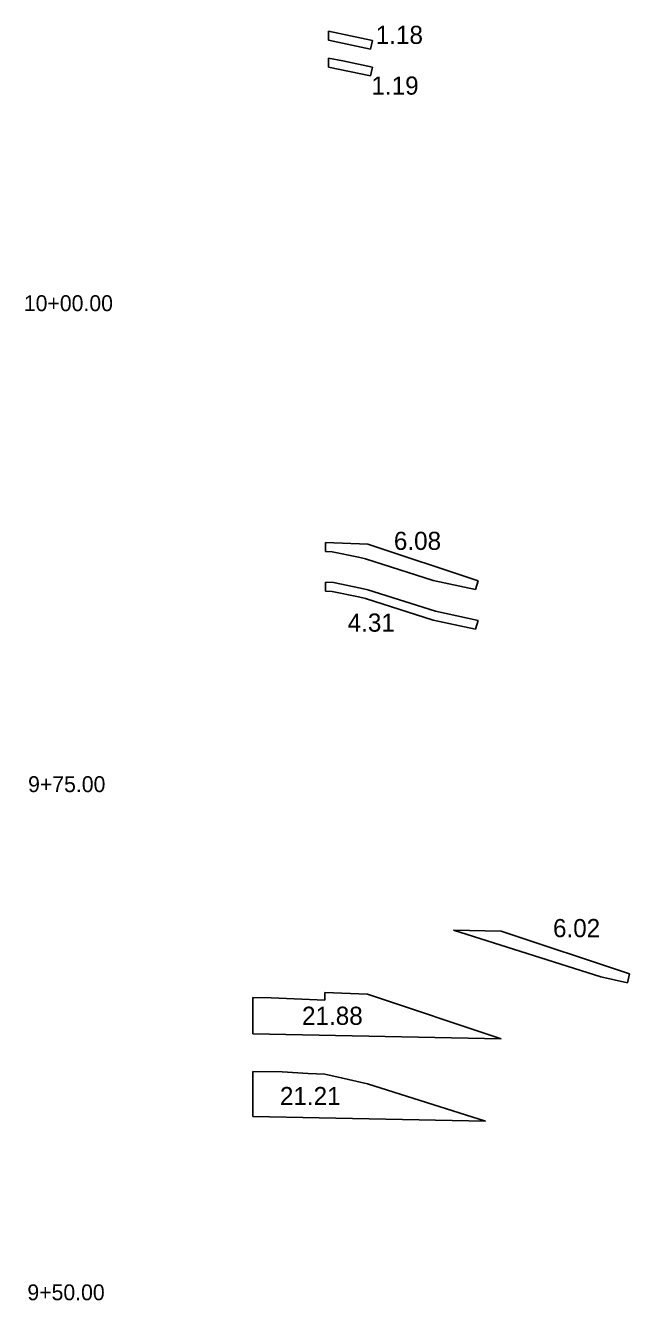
# Model space of a CAD drawing. Extents: x 2194738 to 2195190, y 863888 to 863998.
# Drawn here: x 2194737.6 to 2194770.9, y 863895.1 to 863965.3 of the extents above; entities that cross this region are included whole.
import ezdxf

# ---------------------------------------------------------------- set-up
doc = ezdxf.new("R2010")
doc.units = 0
for name, color, linetype in [('Approach', 7, 'Continuous'), ('H_V ANNOTATION', 7, 'Continuous'), ('S_Roadway_Centerline', 7, 'Continuous'), ('TEMPLATE', 7, 'Continuous')]:
    doc.layers.add(name, color=color, linetype=linetype)

msp = doc.modelspace()

# ---------------------------------------------------------------- linework, layer by layer
at = {"layer": 'S_Roadway_Centerline'}
for points in [[(2194754.353, 863963.517), (2194755.134, 863963.356), (2194756.768, 863963.011)], [(2194754.621, 863934.625), (2194756.106, 863934.311), (2194756.523, 863934.214), (2194760.247, 863933.034), (2194762.606, 863932.521)], [(2194750.176, 863907.678), (2194751.8, 863907.66), (2194753.226, 863907.572), (2194754.139, 863907.522), (2194755.051, 863907.329), (2194756.506, 863906.993), (2194763.003, 863904.934)]]:
    msp.add_lwpolyline(points, dxfattribs=at)
at = {"layer": 'TEMPLATE'}
for p, q in [((2194754.353, 863964.997), (2194756.768, 863964.491)), ((2194756.768, 863964.491), (2194756.668, 863964.012)), ((2194756.768, 863963.011), (2194756.668, 863962.532)), ((2194754.185, 863936.827), (2194754.185, 863936.702)), ((2194754.185, 863936.827), (2194756.523, 863936.734)), ((2194756.523, 863936.734), (2194762.606, 863934.706)), ((2194754.185, 863934.643), (2194754.185, 863934.518)), ((2194754.185, 863934.643), (2194754.621, 863934.625)), ((2194763.878, 863915.412), (2194761.236, 863915.465)), ((2194770.948, 863913.056), (2194770.841, 863912.567)), ((2194756.506, 863911.933), (2194754.139, 863912.028)), ((2194754.139, 863911.611), (2194754.139, 863912.028)), ((2194751.176, 863911.73), (2194750.176, 863911.75)), ((2194750.176, 863909.75), (2194750.176, 863911.75)), ((2194754.139, 863911.611), (2194751.176, 863911.73)), ((2194763.878, 863909.476), (2194750.176, 863909.75)), ((2194750.176, 863905.191), (2194750.176, 863907.678)), ((2194763.003, 863904.934), (2194750.176, 863905.191))]:
    msp.add_line(p, q, dxfattribs=at)
for points in [[(2194754.353, 863964.997), (2194754.353, 863964.497), (2194756.668, 863964.012)], [(2194754.353, 863963.517), (2194754.353, 863963.017), (2194756.668, 863962.532)], [(2194754.185, 863936.702), (2194754.185, 863936.327), (2194754.556, 863936.312)], [(2194754.556, 863936.312), (2194755.998, 863936.007), (2194756.391, 863935.916), (2194760.119, 863934.735), (2194762.447, 863934.229)], [(2194754.185, 863934.518), (2194754.185, 863934.143), (2194754.556, 863934.128)], [(2194762.447, 863934.229), (2194762.606, 863934.706)], [(2194754.556, 863934.128), (2194755.998, 863933.823), (2194756.391, 863933.732), (2194760.119, 863932.551), (2194762.447, 863932.044)], [(2194762.447, 863932.044), (2194762.606, 863932.521)], [(2194761.236, 863915.465), (2194769.374, 863912.886), (2194770.841, 863912.567)], [(2194763.878, 863915.412), (2194770.948, 863913.056)], [(2194756.506, 863911.933), (2194763.878, 863909.476)]]:
    msp.add_lwpolyline(points, dxfattribs=at)

# ---------------------------------------------------------------- texts
at = {"layer": 'Approach'}
for s, p in [('1.18', (2194756.952, 863964.293)), ('1.19', (2194756.715, 863961.498)), ('6.08', (2194757.952, 863936.414)), ('4.31', (2194755.403, 863931.91)), ('6.02', (2194766.727, 863915.077)), ('21.88', (2194752.887, 863910.246)), ('21.21', (2194751.667, 863905.823))]:
    msp.add_text(s, height=1.0002, dxfattribs=at).set_placement(p)
at = {"layer": 'H_V ANNOTATION'}
for s, p in [('10+00.00', (2194737.546, 863949.571)), ('9+75.00', (2194737.78, 863923.071)), ('9+50.00', (2194737.741, 863895.071))]:
    msp.add_text(s, height=0.875, dxfattribs=at).set_placement(p)

doc.saveas('drawing.dxf')
